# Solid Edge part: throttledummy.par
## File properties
Author: morva
Template: iso metric part.par
Last saved by: morva
Revision: 4
Application: Solid Edge
Username: morva
Density: 1776.86616150351 kg/m^3
Accuracy: 0.990
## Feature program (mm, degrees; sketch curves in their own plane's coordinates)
sketch for "unnamed Protrusion 1" #1 plane through (0, 0, 0) normal (0, 0, 1) x-axis (1, 0, 0)
  circle centre (0, 0) radius 11
sketch for "unnamed Protrusion 1" #2 plane through (0, 0, 0) normal (0, 0, 1) x-axis (1, 0, 0)
  line (-21.168, 3.7639) -> (-41.5, 3.7639)
  line (-41.5, 3.7639) -> (-41.5, -3.7639)
  line (-41.5, -3.7639) -> (-21.168, -3.7639)
extrude "unnamed Protrusion 1" add finite 23 along +normal
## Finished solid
Body 1: solid body, 7 faces, 14 edges, 8 vertices.
  Faces by surface: plane 5, cylinder 2
  Edges by curve: line 10, circle 4
Bounding box of the edges (mm): 63.000 x 43.000 x 23.000, from (-41.5, -21.5, 0) to (21.5, 21.5, 23).
Cylindrical faces by radius (mm): R11 x1, R21.5 x1
Planar faces by outward normal: +y 1, +z 1, -x 1, -y 1, -z 1
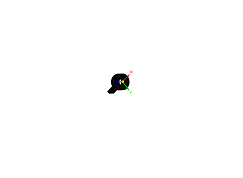
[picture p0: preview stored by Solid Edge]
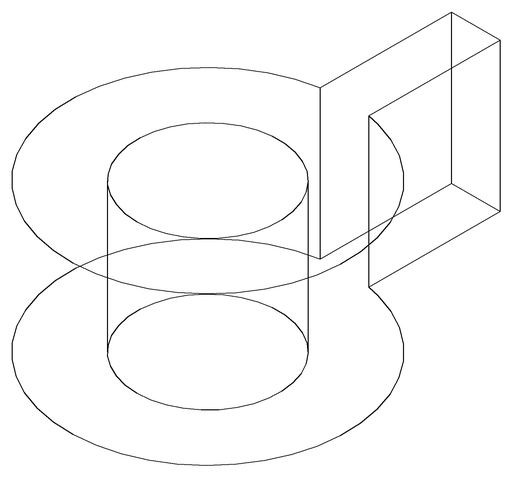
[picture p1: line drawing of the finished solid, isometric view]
